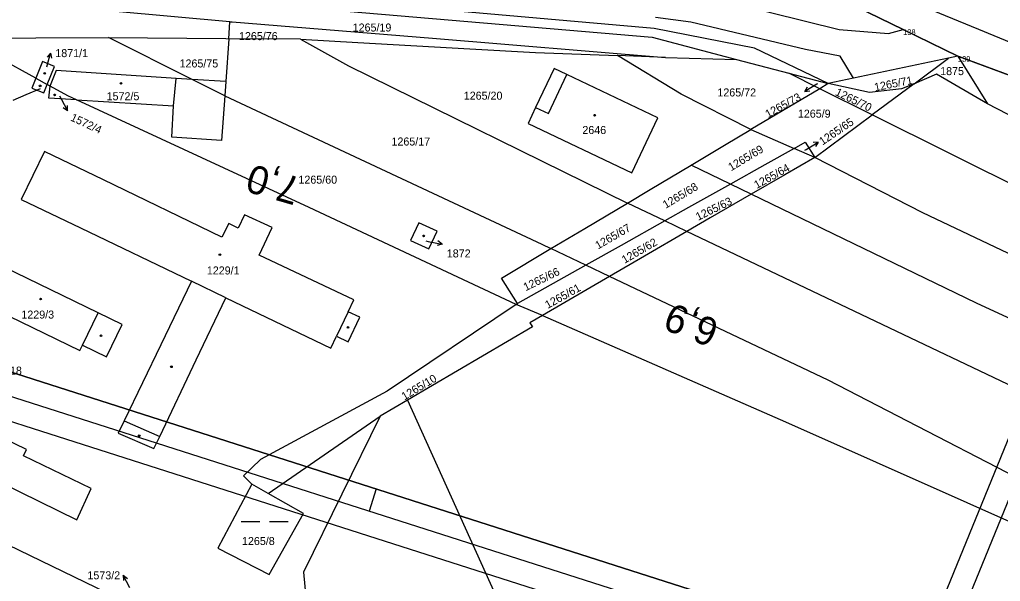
# Model space of a CAD drawing. Extents: x -779330 to -774454, y -1144748 to -1142831.
# Drawn here: x -777170.1 to -776961.8, y -1143987.9 to -1143868.6 of the extents above; entities that cross this region are included whole.
import ezdxf

# ---------------------------------------------------------------- set-up
doc = ezdxf.new("R2010")
doc.units = 0
for name, color, linetype in [('Hranice parcel', 7, 'Continuous'), ('Parcelní čísla', 7, 'Continuous'), ('Pop  PČ popisy', 7, 'Continuous'), ('SŽDC', 7, 'Continuous'), ('Vnitřní kresba', 7, 'Continuous'), ('Vrstva 1', 7, 'Continuous'), ('Vrstva 53', 7, 'Continuous'), ('Vrstva 60', 7, 'Continuous'), ('Vrstva 7', 7, 'Continuous'), ('Značky budov', 7, 'Continuous'), ('Značky kultur', 7, 'Continuous')]:
    doc.layers.add(name, color=color, linetype=linetype)

msp = doc.modelspace()

# ---------------------------------------------------------------- linework, layer by layer
at = {"layer": 'Hranice parcel'}
for p, q in [((-777125.43, -1143869.09), (-777184.32, -1143863.79)), ((-777125.68, -1143872.67), (-777125.43, -1143869.09)), ((-777125.43, -1143869.09), (-777124.98, -1143869.13)), ((-777151.21, -1143872.43), (-777126.28, -1143872.66)), ((-777126.28, -1143872.66), (-777125.68, -1143872.67)), ((-777110.44, -1143872.81), (-777125.68, -1143872.67)), ((-777032.92, -1143876.65), (-777043.14, -1143876.21)), ((-777032.92, -1143876.65), (-777017.82, -1143877.1)), ((-777017.82, -1143877.1), (-777006.74, -1143880.02)), ((-776980.14, -1143882.23), (-776972.79, -1143876.78)), ((-776970.83, -1143876.37), (-776972.79, -1143876.78)), ((-776970.83, -1143876.37), (-776964.5, -1143886.48)), ((-777006.74, -1143880.02), (-776998.39, -1143882.22)), ((-777000.18, -1143883.29), (-777006.74, -1143880.02)), ((-777166.67, -1143881.06), (-777164.25, -1143882.39)), ((-776998.39, -1143882.22), (-777000.18, -1143883.29)), ((-776980.14, -1143882.23), (-776989.05, -1143888.84)), ((-777163.6, -1143882.75), (-777164.25, -1143882.39)), ((-777000.18, -1143883.29), (-777014.77, -1143891.96)), ((-776989.05, -1143888.84), (-777000.18, -1143883.29)), ((-777001.23, -1143897.87), (-776989.05, -1143888.84)), ((-777014.77, -1143891.96), (-777005.59, -1143895.97)), ((-777001.23, -1143897.87), (-777005.59, -1143895.97)), ((-777019.12, -1143903.55), (-777027.46, -1143899.52)), ((-777014.7, -1143905.69), (-777019.12, -1143903.55)), ((-777033.09, -1143911.38), (-777041.02, -1143907.6)), ((-777028.37, -1143913.63), (-777033.09, -1143911.38)), ((-777049.85, -1143920.77), (-777057.27, -1143917.26)), ((-777049.85, -1143920.77), (-777064.35, -1143928.9)), ((-777044.79, -1143923.17), (-777049.85, -1143920.77)), ((-777044.79, -1143923.17), (-777059.08, -1143931.47)), ((-777064.63, -1143929.09), (-777064.35, -1143928.9)), ((-777059.08, -1143931.47), (-777064.63, -1143929.09)), ((-777087.76, -1143949.47), (-777093.52, -1143952.82)), ((-777087.76, -1143949.47), (-777045.94, -1144041.58)), ((-777117.31, -1143969.24), (-777093.52, -1143952.82)), ((-777117.31, -1143969.24), (-777120.78, -1143967.25))]:
    msp.add_line(p, q, dxfattribs=at)
for points in [[(-776998.39, -1143882.22), (-777014.02, -1143874.66), (-777035.36, -1143870.54), (-777167.58, -1143858.82), (-777281.88, -1143848.9), (-777289.53, -1143848.43), (-777292.27, -1143847.75), (-777303.16, -1143845.03)], [(-777211.92, -1143858.84), (-777211.13, -1143856.84), (-777167.5, -1143860.96), (-777150.77, -1143862.48), (-777035.76, -1143872.38), (-777017.82, -1143877.1)], [(-777002.25, -1143861.05), (-776982.48, -1143870.69), (-776970.83, -1143876.37)], [(-777124.98, -1143869.13), (-777082.45, -1143872.54), (-777032.92, -1143876.65)], [(-777166.67, -1143881.06), (-777182.17, -1143872.56), (-777151.21, -1143872.43)], [(-777126.53, -1143884.78), (-777133.48, -1143881.32), (-777151.21, -1143872.43)], [(-777125.68, -1143872.67), (-777126.32, -1143881.78), (-777126.53, -1143884.78)], [(-777110.44, -1143872.81), (-777100.29, -1143878.41), (-777041.02, -1143907.6)], [(-777110.44, -1143872.81), (-777098.28, -1143873.49), (-777074.51, -1143874.84), (-777060.56, -1143875.59), (-777043.14, -1143876.21)], [(-777164.25, -1143882.39), (-777162.69, -1143878.57), (-777165.23, -1143877.53), (-777166.67, -1143881.06)], [(-777014.77, -1143891.96), (-777029.58, -1143884.49), (-777043.14, -1143876.21)], [(-776972.79, -1143876.78), (-776992.99, -1143881.07), (-776998.39, -1143882.22)], [(-776970.83, -1143876.37), (-776959.34, -1143880.62), (-776893.47, -1143907.54), (-776747.29, -1143966.09)], [(-777158.02, -1143885.65), (-777137.41, -1143886.96), (-777136.87, -1143881.1), (-777162.34, -1143879.46), (-777163.59, -1143882.64), (-777163.6, -1143882.75)], [(-777053.88, -1143880.29), (-777056.58, -1143879.03), (-777060.52, -1143887.31), (-777062.13, -1143890.66), (-777040.08, -1143901.18), (-777034.53, -1143889.5), (-777053.88, -1143880.29)], [(-777166.67, -1143881.06), (-777167.52, -1143883.15), (-777164.98, -1143884.18), (-777164.25, -1143882.39)], [(-776980.14, -1143882.23), (-776982.79, -1143883.35), (-776989.59, -1143884.09), (-776998.39, -1143882.22)], [(-776964.5, -1143886.48), (-776975.37, -1143880.22), (-776980.14, -1143882.23)], [(-777158.02, -1143885.65), (-777163.88, -1143885.28), (-777163.6, -1143882.75)], [(-777158.02, -1143885.65), (-777159.84, -1143884.81), (-777163.6, -1143882.75)], [(-777064.63, -1143929.09), (-777108.64, -1143908.55), (-777158.02, -1143885.65)], [(-777126.53, -1143884.78), (-777059.22, -1143916.33), (-777057.27, -1143917.26)], [(-776767.95, -1143981.96), (-776771.13, -1143981.54), (-776923.23, -1143907.82), (-776964.5, -1143886.48)], [(-776817.86, -1143983.94), (-776814.26, -1143974.07), (-776869.06, -1143948.13), (-776905.56, -1143930.42), (-776989.05, -1143888.84)], [(-777027.46, -1143899.52), (-777020.38, -1143895.3), (-777014.77, -1143891.96)], [(-777005.59, -1143895.97), (-777003.26, -1143894.66), (-777001.23, -1143897.87)], [(-777122.34, -1143910.06), (-777123.69, -1143912.92), (-777125.66, -1143911.89), (-777127.18, -1143914.79), (-777152.28, -1143902.66), (-777164.83, -1143896.6), (-777169.76, -1143906.8), (-777157.17, -1143912.85), (-777133.63, -1143924.16), (-777140.15, -1143937.67), (-777147.94, -1143953.83), (-777149.2, -1143956.43), (-777141.61, -1143959.73), (-777140.36, -1143957.12), (-777132.6, -1143940.84), (-777126.31, -1143927.68), (-777103.98, -1143938.41), (-777102.79, -1143935.87), (-777100.33, -1143937.03), (-777097.85, -1143931.84), (-777100.35, -1143930.67), (-777099.16, -1143928.16), (-777119.25, -1143918.66), (-777116.5, -1143912.8), (-777122.34, -1143910.06)], [(-777005.59, -1143895.97), (-777011.86, -1143899.48), (-777019.12, -1143903.55)], [(-777001.23, -1143897.87), (-777007.6, -1143901.57), (-777014.7, -1143905.69)], [(-776819.3, -1143987.88), (-776871.91, -1143959.94), (-776915.87, -1143938.7), (-776942.03, -1143926.84), (-776978.29, -1143909.65), (-777001.23, -1143897.87)], [(-777041.02, -1143907.6), (-777036.15, -1143904.69), (-777027.46, -1143899.52)], [(-777019.12, -1143903.55), (-777028.04, -1143908.55), (-777033.09, -1143911.38)], [(-777014.7, -1143905.69), (-777023.42, -1143910.75), (-777028.37, -1143913.63)], [(-776828.14, -1143996.73), (-776887.84, -1143965.39), (-776966.84, -1143928.84), (-777014.7, -1143905.69)], [(-777057.27, -1143917.26), (-777050.08, -1143912.98), (-777041.02, -1143907.6)], [(-777033.09, -1143911.38), (-777042.34, -1143916.56), (-777049.85, -1143920.77)], [(-777081.43, -1143913.56), (-777085.29, -1143911.77), (-777087.1, -1143915.56), (-777083.22, -1143917.29), (-777081.43, -1143913.56)], [(-777028.37, -1143913.63), (-777037.37, -1143918.86), (-777044.79, -1143923.17)], [(-776843.21, -1144004.32), (-776917.2, -1143966.59), (-777028.37, -1143913.63)], [(-777064.35, -1143928.9), (-777067.77, -1143923.5), (-777057.27, -1143917.26)], [(-777153.45, -1143930.87), (-777176.1, -1143919.92), (-777179.97, -1143927.94), (-777157.35, -1143938.91), (-777156.78, -1143937.74), (-777151.69, -1143940.24), (-777148.31, -1143933.36), (-777153.45, -1143930.87)], [(-776864.86, -1144013.82), (-776884.37, -1144004.05), (-776998.38, -1143945.16), (-777044.79, -1143923.17)], [(-777064.63, -1143929.09), (-777092.08, -1143947.56), (-777118.97, -1143962.02), (-777122.57, -1143965.52), (-777120.78, -1143967.25)], [(-777059.08, -1143931.47), (-777061.75, -1143933.02), (-777061.19, -1143933.89), (-777087.76, -1143949.47)], [(-777059.08, -1143931.47), (-777007.46, -1143954.02), (-776949.67, -1143979.74), (-776875.92, -1144018.96)], [(-777242.24, -1143946.21), (-777233.61, -1143950.34), (-777182.11, -1143975.59), (-777151.49, -1143990.35)], [(-777176.5, -1143957.76), (-777190.89, -1143950.8), (-777194.08, -1143949.25), (-777197.24, -1143955.62), (-777194.04, -1143957.18), (-777157.99, -1143974.82), (-777154.93, -1143968.2), (-777169.31, -1143961.24), (-777168.67, -1143959.91), (-777175.86, -1143956.43), (-777176.5, -1143957.76)], [(-777093.52, -1143952.82), (-777109.82, -1143985.95), (-777109.29, -1143991.28), (-777097.63, -1144016.39)], [(-777120.78, -1143967.25), (-777128.02, -1143980.84), (-777117.13, -1143986.44), (-777109.82, -1143973.51), (-777117.31, -1143969.24)]]:
    msp.add_lwpolyline(points, dxfattribs=at)
at = {"layer": 'Pop  PČ popisy'}
for p, q in [((-777164.31, -1143878.64), (-777163.53, -1143875.74)), ((-777163.53, -1143875.74), (-777164.28, -1143876.58)), ((-777163.53, -1143875.74), (-777163.31, -1143876.84)), ((-777164.32, -1143878.66), (-777164.31, -1143878.64)), ((-777000.66, -1143882.24), (-777000.78, -1143882.32)), ((-777165.75, -1143883.32), (-777168.78, -1143884.63)), ((-777000.78, -1143882.32), (-777003.35, -1143883.87)), ((-777003.35, -1143883.87), (-777002.75, -1143882.92)), ((-777003.35, -1143883.87), (-777002.24, -1143883.78)), ((-777168.78, -1143884.63), (-777171.54, -1143885.8)), ((-777161.62, -1143884.81), (-777161.34, -1143885.33)), ((-777161.34, -1143885.33), (-777159.93, -1143887.98)), ((-777159.93, -1143887.98), (-777160.84, -1143887.33)), ((-777159.93, -1143887.98), (-777159.96, -1143886.86)), ((-777003.05, -1143896.19), (-777000.48, -1143894.64)), ((-777000.48, -1143894.64), (-777001.59, -1143894.73)), ((-777000.48, -1143894.64), (-777001.08, -1143895.59)), ((-777003.35, -1143896.37), (-777003.05, -1143896.19)), ((-777083.82, -1143915.63), (-777083.32, -1143915.73)), ((-777083.32, -1143915.73), (-777080.37, -1143916.3)), ((-777080.37, -1143916.3), (-777081.45, -1143916.6)), ((-777080.37, -1143916.3), (-777081.26, -1143915.62)), ((-777146.69, -1143989.28), (-777148.1, -1143986.63)), ((-777148.1, -1143986.63), (-777147.19, -1143987.28)), ((-777148.1, -1143986.63), (-777148.07, -1143987.75))]:
    msp.add_line(p, q, dxfattribs=at)
at = {"layer": 'SŽDC'}
for points in [[(-777171.85, -1143806.53), (-777132.17, -1143818.13), (-777116.14, -1143822.78), (-777098, -1143828.05), (-777084.01, -1143832.11), (-777070.84, -1143836.27), (-777043.81, -1143845.48), (-777016.74, -1143855.53), (-777002.25, -1143861.05), (-776982.48, -1143870.69)], [(-776982.48, -1143870.69), (-776970.83, -1143876.37), (-776959.34, -1143880.62), (-776893.47, -1143907.54), (-776747.29, -1143966.09), (-776712.36, -1143980.08), (-776627.91, -1144012.39), (-776609.89, -1144021.72)]]:
    msp.add_lwpolyline(points, dxfattribs=at)
at = {"layer": 'Vnitřní kresba'}
for p, q in [((-777018.06, -1143865.29), (-776996.07, -1143870.7)), ((-777027.55, -1143869.14), (-777035.05, -1143868.16)), ((-777003.19, -1143875), (-777027.55, -1143869.14)), ((-776996.07, -1143870.7), (-776985.59, -1143871.58)), ((-776985.59, -1143871.58), (-776982.48, -1143870.69)), ((-776995.85, -1143876.42), (-777003.19, -1143875)), ((-776992.99, -1143881.07), (-776995.85, -1143876.42)), ((-777133.48, -1143881.32), (-777136.87, -1143881.1)), ((-777126.32, -1143881.78), (-777133.48, -1143881.32)), ((-777057.81, -1143888.59), (-777053.88, -1143880.29)), ((-777126.53, -1143884.78), (-777127.2, -1143894.33)), ((-777137.77, -1143893.58), (-777137.41, -1143886.96)), ((-777060.52, -1143887.31), (-777057.81, -1143888.59)), ((-777127.2, -1143894.33), (-777137.77, -1143893.58)), ((-777126.31, -1143927.68), (-777133.63, -1143924.16)), ((-777156.78, -1143937.74), (-777153.45, -1143930.87)), ((-777100.35, -1143930.67), (-777102.79, -1143935.87)), ((-777147.94, -1143953.83), (-777140.36, -1143957.12))]:
    msp.add_line(p, q, dxfattribs=at)
at = {"layer": 'Vrstva 1'}
msp.add_line((-777094.38, -1143968.26), (-777095.9, -1143973.02), dxfattribs=at)
for points in [[(-776606.88, -1143822.95), (-777806.9, -1143438.86), (-777897.43, -1143721.71), (-776697.42, -1144105.81)], [(-776700.65, -1144099.52), (-777891.15, -1143718.47), (-777803.66, -1143445.14), (-776613.17, -1143826.19)], [(-776619.45, -1143829.42), (-777605.19, -1143513.91), (-777689.63, -1143777.73), (-776703.89, -1144093.24)], [(-776703.89, -1144093.24), (-777689.63, -1143777.73), (-777605.19, -1143513.91), (-776619.45, -1143829.42)], [(-775713.68, -1144238.31), (-776879.99, -1143761.57), (-776992.36, -1144036.48), (-775826.05, -1144513.22)], [(-775828.78, -1144506.7), (-776985.84, -1144033.74), (-776877.25, -1143768.09), (-775720.2, -1144241.05)]]:
    msp.add_lwpolyline(points, close=True, dxfattribs=at)
msp.add_lwpolyline([(-776598.67, -1144021.52), (-776616.38, -1144014.26), (-776631.53, -1144008.05), (-776654.6, -1143998.59), (-776677.94, -1143989.03), (-776699.16, -1143980.33), (-776719.94, -1143971.81), (-776741.24, -1143963.08), (-776767.06, -1143952.49), (-776786.63, -1143944.47), (-776802.02, -1143938.15), (-776814.7, -1143932.96), (-776837.62, -1143923.56), (-776863.52, -1143912.95), (-776887.51, -1143903.12), (-776902.63, -1143896.92), (-776922.15, -1143888.92), (-776942.01, -1143880.78), (-776966.41, -1143870.74), (-776976.22, -1143866.7)], dxfattribs=at)
at = {"layer": 'Vrstva 53'}
for points in [[(-776982.48, -1143870.69), (-777002.25, -1143861.05), (-777016.74, -1143855.53), (-777043.81, -1143845.48), (-777070.84, -1143836.27), (-777084.01, -1143832.11), (-777098, -1143828.05), (-777116.14, -1143822.78), (-777132.17, -1143818.13), (-777171.85, -1143806.53)], [(-776982.48, -1143870.69), (-777002.25, -1143861.05), (-777016.74, -1143855.53), (-777043.81, -1143845.48), (-777070.84, -1143836.27), (-777084.01, -1143832.11), (-777098, -1143828.05), (-777116.14, -1143822.78), (-777132.17, -1143818.13), (-777171.85, -1143806.53)], [(-776609.89, -1144021.72), (-776627.91, -1144012.39), (-776712.36, -1143980.08), (-776747.29, -1143966.09), (-776893.47, -1143907.54), (-776959.34, -1143880.62), (-776970.83, -1143876.37), (-776982.48, -1143870.69)], [(-776609.89, -1144021.72), (-776627.91, -1144012.39), (-776712.36, -1143980.08), (-776747.29, -1143966.09), (-776893.47, -1143907.54), (-776959.34, -1143880.62), (-776970.83, -1143876.37), (-776982.48, -1143870.69)]]:
    msp.add_lwpolyline(points, dxfattribs=at)
at = {"layer": 'Vrstva 60'}
for p, q in [((-776982.48, -1143870.69), (-776982.48, -1143870.69)), ((-776970.83, -1143876.37), (-776970.83, -1143876.37))]:
    msp.add_line(p, q, dxfattribs=at)
at = {"layer": 'Značky budov'}
for centre in [(-777164.79, -1143880.04), (-777148.59, -1143882.16), (-777165.76, -1143882.69), (-777162.67, -1143884.61), (-777047.99, -1143888.92), (-777084.3, -1143914.55), (-777127.58, -1143918.53), (-777165.65, -1143927.97), (-777100.36, -1143934), (-777152.82, -1143935.76), (-777137.86, -1143942.35), (-777144.71, -1143957)]:
    msp.add_circle(centre, 0.175, dxfattribs=at)
at = {"layer": 'Značky kultur'}
for p, q in [((-777123.09, -1143975.19), (-777119.07, -1143975.19)), ((-777117.06, -1143975.19), (-777113.04, -1143975.19))]:
    msp.add_line(p, q, dxfattribs=at)

# ---------------------------------------------------------------- texts
at = {"layer": 'Parcelní čísla'}
for s, p in [('1265/19', (-777099.37, -1143871.15)), ('1265/76', (-777123.52, -1143872.98)), ('1871/1', (-777162.53, -1143876.59)), ('1265/75', (-777136.14, -1143878.78)), ('1875', (-776974.59, -1143880.41)), ('1572/5', (-777151.63, -1143885.75)), ('1265/20', (-777075.78, -1143885.63)), ('1265/72', (-777021.91, -1143884.94)), ('1265/9', (-777004.81, -1143889.45)), ('2646', (-777050.59, -1143892.92)), ('1265/17', (-777091.13, -1143895.36)), ('1265/60', (-777110.89, -1143903.46)), ('1872', (-777079.38, -1143919.13)), ('1229/1', (-777130.35, -1143922.74)), ('1229/3', (-777169.74, -1143932.11)), ('1265/18', (-777177.85, -1143944.01)), ('1265/8', (-777122.88, -1143980.2)), ('1573/2', (-777155.71, -1143987.48))]:
    msp.add_text(s, height=1.7, dxfattribs=at).set_placement(p)
for s, rotation, p in [('1265/71', 11, (-776988.41, -1143883.84)), ('1265/73', 29, (-777011.16, -1143889.56)), ('1265/70', 334, (-776997.03, -1143884.59)), ('1572/4', 335, (-777159.46, -1143889.99)), ('1265/65', 34, (-776999.58, -1143895.37)), ('1265/69', 31, (-777018.98, -1143900.84)), ('1265/64', 29, (-777013.54, -1143904.61)), ('1265/68', 31, (-777032.88, -1143908.82)), ('1265/63', 26, (-777026, -1143911.36)), ('1265/67', 30, (-777047.26, -1143917.46)), ('1265/62', 30, (-777041.62, -1143920.49)), ('1265/66', 26, (-777062.61, -1143926.31)), ('1265/61', 29, (-777057.94, -1143930.08)), ('1265/10', 31, (-777088.38, -1143949.52))]:
    msp.add_text(s, height=1.7, rotation=rotation, dxfattribs=at).set_placement(p)
at = {"layer": 'Vrstva 60'}
for s, p in [('138', (-776982.48, -1143871.89)), ('139', (-776970.83, -1143877.57))]:
    msp.add_text(s, height=1.2, dxfattribs=at).set_placement(p)
at = {"layer": 'Vrstva 7'}
for s, rotation, p in [('7,0', 163.8343, (-777110.07, -1143902.34)), ('6,9', 158.4292, (-777021.17, -1143932.74))]:
    msp.add_text(s, height=6, rotation=rotation, dxfattribs=at).set_placement(p)

doc.saveas('drawing.dxf')
